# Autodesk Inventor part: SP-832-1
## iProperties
Author: Ron Crain
Shininess: 85.0
Length Units: 11272
Angle Units: 11286
Time Units: 11279
Mass Units: 11290
Length Display Precision: 2
Angle Display Precision: 1
Compacted: True
PropertySet Name: _Private Model Information
Created: 2001-02
Part Number: SP-832-1
Material: Stainless Steel, Austenitic
Description: NUT, SELF CLINCH, TYPE SP, 8-32 UNC
Vendor: PENN MFG. & ENG
Document SubType Name: Modeling
Designer: Ron Crain
Control State: 0
Master: False
Checked Out: False
PropertySet Name: Design Tracking Control
Density: 0.0
Volumn: 0.0
Area: 0.0
PropertySet Name: Model Information
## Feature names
1. Revolution1
